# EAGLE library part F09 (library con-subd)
SUB-D
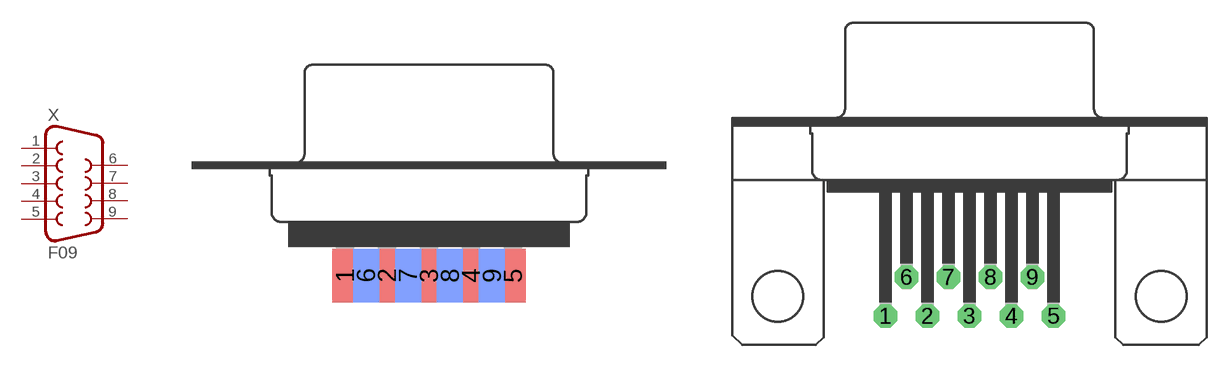
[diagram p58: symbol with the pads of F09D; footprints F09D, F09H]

Designator prefix X

## F09D (OC_FARNELL: unknown; OC_NEWARK: unknown)  [F09D]
1  1  pas
2  2  pas
3  3  pas
4  4  pas
5  5  pas
6  6  pas
7  7  pas
8  8  pas
9  9  pas

## F09H (OC_FARNELL: unknown; OC_NEWARK: unknown)  [F09H]
Pads as for F09D

## F09HP (OC_FARNELL: unknown; OC_NEWARK: unknown)  [F09HP]
Pads as for F09D

## F09V (OC_FARNELL: unknown; OC_NEWARK: unknown)  [F09V]
Pads as for F09D

## F09VP (OC_FARNELL: unknown; OC_NEWARK: unknown)  [F09VP]
Pads as for F09D

## F09VB (OC_FARNELL: unknown; OC_NEWARK: unknown)  [F09VB]
Pads as for F09D

## Footprint F09D (pad centres in mm)
SUB-D
smd 1.7 x 3.5: 1 -5.486,-6.045; 2 -2.743,-6.045; 3 0,-6.045; 4 2.743,-6.045; 5 5.486,-6.045
smd 1.7 x 3.5 bottom: 6 -4.115,-6.045; 7 -1.372,-6.045; 8 1.372,-6.045; 9 4.115,-6.045

## Footprint F09H (pad centres in mm)
SUB-D
drill 1.016 octagon: 1 -5.486,-1.27; 2 -2.743,-1.27; 3 0,-1.27; 4 2.743,-1.27; 5 5.486,-1.27; 6 -4.115,1.27; 7 -1.372,1.27; 8 1.372,1.27; 9 4.115,1.27
hole 3.302 at -12.522,0
hole 3.302 at 12.522,0

## Footprint F09HP (pad centres in mm)
SUB-D
drill 1.016 octagon: 1 -5.486,-1.27; 2 -2.743,-1.27; 3 0,-1.27; 4 2.743,-1.27; 5 5.486,-1.27; 6 -4.115,1.27; 7 -1.372,1.27; 8 1.372,1.27; 9 4.115,1.27
drill 3.302 pad 5.08 round: G1 -12.522,0; G2 12.522,0

## Footprint F09V (pad centres in mm)
SUB-D
drill 1.016 octagon: 1 5.486,1.422; 2 2.743,1.422; 3 0,1.422; 4 -2.743,1.422; 5 -5.486,1.422; 6 4.115,-1.422; 7 1.372,-1.422; 8 -1.372,-1.422; 9 -4.115,-1.422
hole 3.302 at -12.522,0
hole 3.302 at 12.522,0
